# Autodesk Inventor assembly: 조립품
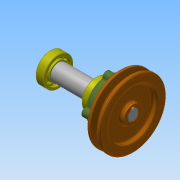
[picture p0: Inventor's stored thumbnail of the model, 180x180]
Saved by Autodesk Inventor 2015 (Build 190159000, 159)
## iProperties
Created: 2019-12
Part Number: 조립품
Document SubType Name: Assembly
Designer: user
Author: user
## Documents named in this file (8)
- C:\Users\user\Desktop\491204V1063\조립품.iam
- C:\Users\user\Desktop\491204V1063\본체.ipt
- C:\Users\user\Desktop\491204V1063\커버.ipt
- C:\Users\user\Desktop\491204V1063\오일 실.ipt
- C:\Users\user\Desktop\491204V1063\베어링 6004.ipt
- C:\Users\user\Desktop\491204V1063\축.ipt
- C:\Users\user\Desktop\491204V1063\키 5 x 5 x 16.ipt
- C:\Users\user\Desktop\491204V1063\V벨트풀리.ipt
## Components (1 placed, 1 different names)
1. V벨트풀리:1
